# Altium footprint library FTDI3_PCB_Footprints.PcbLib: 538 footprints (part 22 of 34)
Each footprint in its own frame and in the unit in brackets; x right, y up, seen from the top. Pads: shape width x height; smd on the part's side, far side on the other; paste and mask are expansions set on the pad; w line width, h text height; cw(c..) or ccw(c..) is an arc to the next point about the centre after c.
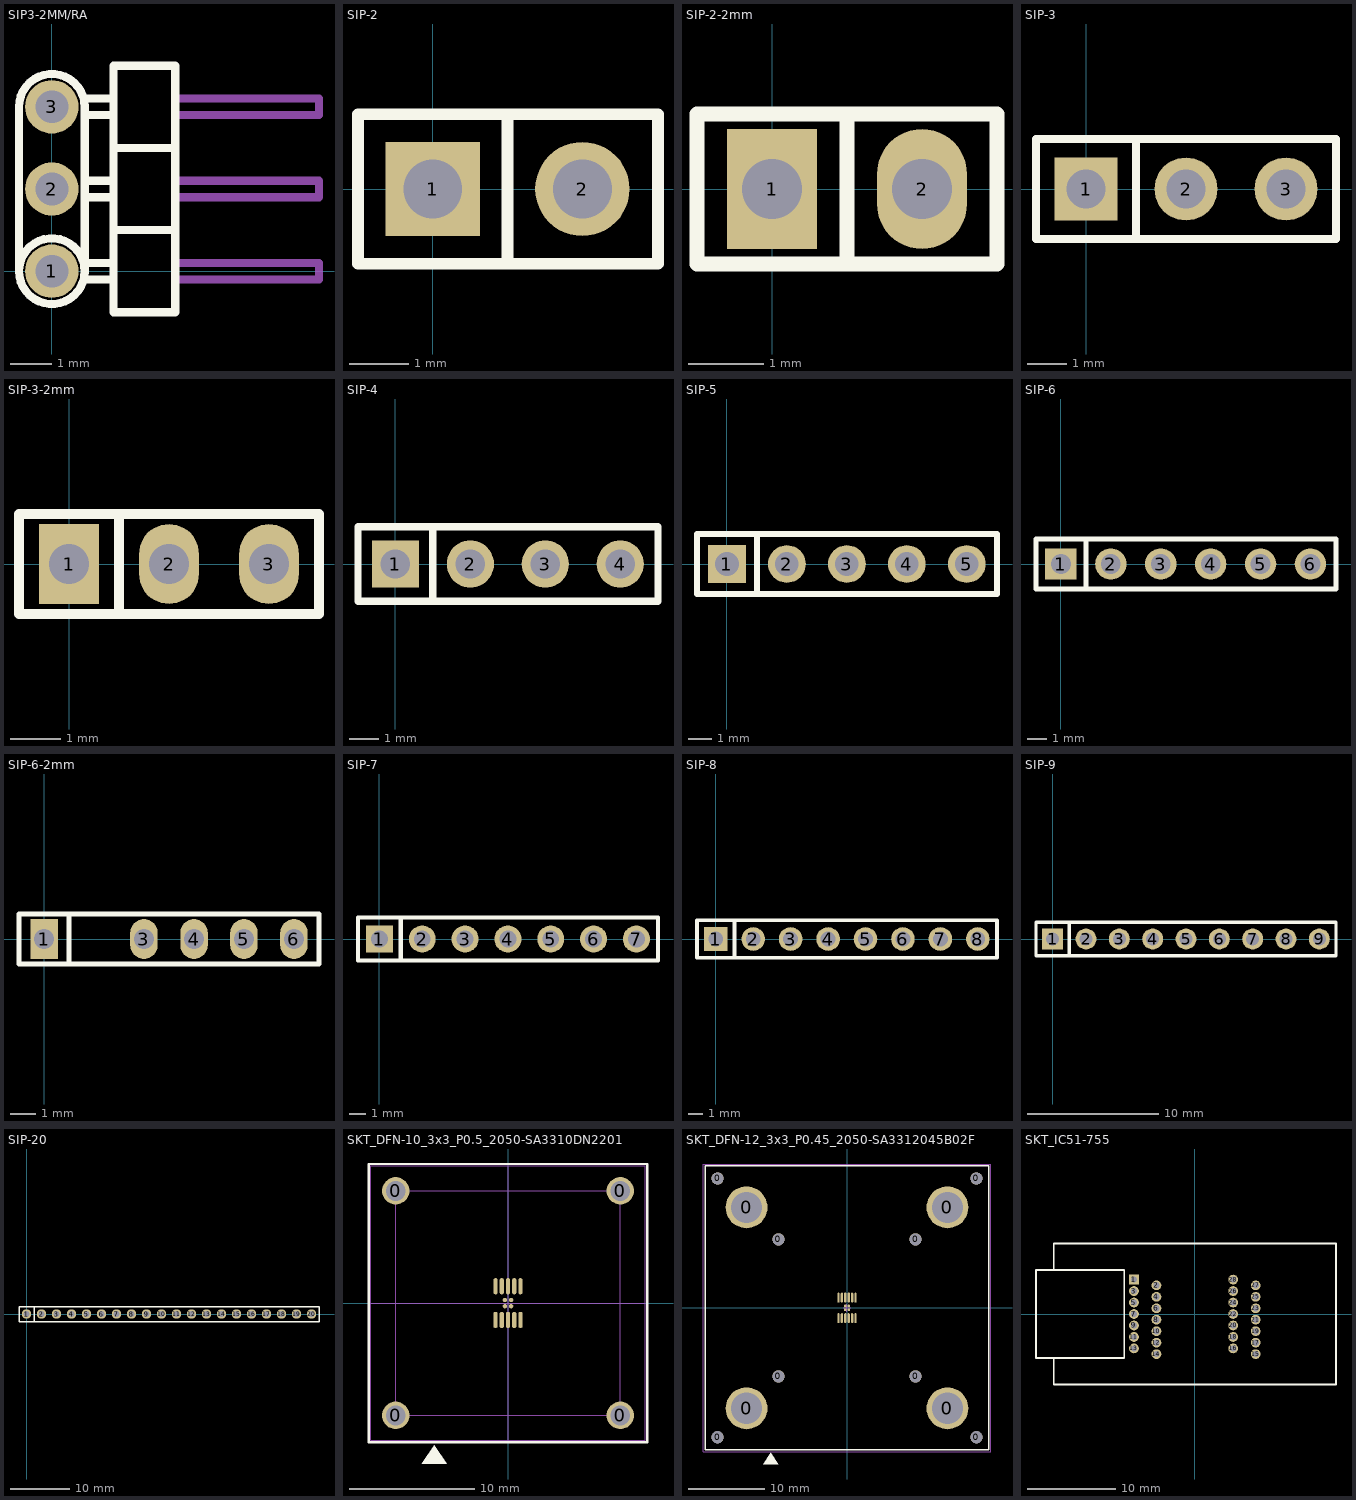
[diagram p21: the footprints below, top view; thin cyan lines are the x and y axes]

## SIP3-2MM/RA [mm] "Right Angle 2mm 3 way header"
pads (3):
  round 1.3 hole 0.8: 1(0,0) 2(0,2) 3(0,4)
Top Overlay:
  lines w0.2: 0.8,-0.2 1.5,-0.2 ; 0.8,0.2 1.5,0.2 ; 0.8,1.8 1.5,1.8 ; 0.8,2.2 1.5,2.2 ; 0.8,3.8 1.5,3.8 ; 0.8,4.2 1.5,4.2 ; 1.5,1 3,1 ; 1.5,3 3,3 ; -0.8,0 cw(c0,0) 0.8,0 ; -0.8,0 ccw(c0,0) 0.8,0 ; -0.8,0 -0.8,4 cw(c0,4) 0.8,4 0.8,0 ; 1.5,-1 3,-1 3,5 1.5,5 1.5,-1
M13_Assembly_Info:
  lines w0.2: 3,-0.2 6.5,-0.2 6.5,0.2 3,0.2 ; 3,1.8 6.5,1.8 6.5,2.2 3,2.2 ; 3,3.8 6.5,3.8 6.5,4.2 3,4.2

## SIP-2 [mm] "2 possition jumper; 0.1\" pitch"
pads (2):
  rect 1.6x1.6 hole 1: 1(0,0)
  round 1.6 hole 1: 2(2.54,0)
Top Overlay:
  lines w0.2: 1.27,-1.27 1.27,1.27 ; -1.27,-1.27 3.825,-1.27 3.825,1.27 -1.27,1.27 -1.27,-1.27
M13_Assembly_Info:
  lines w0.1: -1.27,-1.27 3.825,-1.27 3.825,1.27 -1.27,1.27 -1.27,-1.27
3D body: height 0, standoff 0, extent -1.27,-1.27 3.825,1.27

## SIP-2-2mm [mm] "Header, 2 pin, pitch 2.0mm"
pads (2):
  rect 1.2x1.6 hole 0.8: 1(0,0)
  oval 1.2x1.6 hole 0.8: 2(2,0)
Top Overlay:
  lines w0.2: 1,-1 1,1 ; -1,-1 3,-1 3,1 -1,1 -1,-1
3D body: height 6.5, standoff 0, extent -0.9,-0.9 2.9,0.9

## SIP-3 [mm] "3 possition jumper; pitch 0.1\""
pads (3):
  rect 1.6x1.6 hole 1: 1(0,0)
  round 1.6 hole 1: 2(2.54,0) 3(5.08,0)
Top Overlay:
  lines w0.2: 1.27,-1.27 1.27,1.27 ; -1.27,-1.27 6.35,-1.27 6.35,1.27 -1.27,1.27 -1.27,-1.27
M13_Assembly_Info:
  lines w0.1: -1.27,-1.27 6.35,-1.27 6.35,1.27 -1.27,1.27 -1.27,-1.27
3D body: height 0, standoff 0, extent -1.27,-1.27 6.35,1.27

## SIP-3-2mm [mm] "Header, 3 pin, pitch 2.0mm"
pads (3):
  rect 1.2x1.6 hole 0.8: 1(0,0)
  oval 1.2x1.6 hole 0.8: 2(2,0) 3(4,0)
Top Overlay:
  lines w0.2: 1,-1 1,1 ; -1,-1 -1,1 5,1 5,-1 -1,-1
3D body: height 6.5, standoff 0, extent -0.9,-0.9 4.9,0.9

## SIP-4 [mm] "Header; 4pin; pitch 0.1\""
pads (4):
  rect 1.6x1.6 hole 1: 1(0,0)
  round 1.6 hole 1: 2(2.54,0) 3(5.08,0) 4(7.62,0)
Top Overlay:
  lines w0.254: 1.27,-1.27 1.27,1.27 ; -1.27,-1.27 8.9,-1.27 8.9,1.27 -1.27,1.27 -1.27,-1.27
3D body: height 6.5, standoff 0, extent -1.15,-1.15 8.77,1.16

## SIP-5 [mm] "Header; 5 pin; pitch 0.1\""
pads (5):
  rect 1.6x1.6 hole 1: 1(0,0)
  round 1.6 hole 1: 2(2.54,0) 3(5.08,0) 4(7.62,0) 5(10.16,0)
Top Overlay:
  lines w0.254: 1.27,-1.27 1.27,1.27 ; -1.27,-1.27 -1.27,1.27 11.44,1.27 11.44,-1.27 -1.27,-1.27
3D body: height 6.5, standoff 0, extent -1.15,-1.15 11.325,1.15

## SIP-6 [mm] "Header, 6 pin, pitch 0.1\""
pads (6):
  rect 1.6x1.6 hole 1: 1(0,0)
  round 1.6 hole 1: 2(2.54,0) 3(5.08,0) 4(7.62,0) 5(10.16,0) 6(12.7,0)
Top Overlay:
  lines w0.254: 1.27,-1.27 1.27,1.27 ; -1.27,-1.27 -1.27,1.27 14,1.27 14,-1.27 -1.27,-1.27
3D body: height 6.5, standoff 0, extent -1.15,-1.15 13.875,1.15

## SIP-6-2mm [mm] "Header, 6 pin, pitch 2.0mm; pin 2 blind; for VII debugger module"
pads (5):
  rect 1.1x1.6 hole 0.8: 1(0,0)
  oval 1.1x1.6 hole 0.8: 3(4,0) 4(6,0) 5(8,0) 6(10,0)
Top Overlay:
  lines w0.2: 1,-1 1,1 ; -1,-1 -1,1 11,1 11,-1 -1,-1
3D body: height 6.5, standoff 0, extent -0.9,-0.9 10.9,0.9

## SIP-7 [mm] "Header, 7 pin, pitch 0.1\""
pads (7):
  rect 1.6x1.6 hole 1: 1(0,0)
  round 1.6 hole 1: 2(2.54,0) 3(5.08,0) 4(7.62,0) 5(10.16,0) 6(12.7,0) 7(15.24,0)
Top Overlay:
  lines w0.254: 1.27,-1.27 1.27,1.27 ; -1.27,-1.27 16.52,-1.27 16.52,1.27 -1.27,1.27 -1.27,-1.27
3D body: height 6.5, standoff 0, extent -1.15,-1.15 16.39,1.15

## SIP-8 [mm] "Header, 8 pin, pitch 0.1\""
pads (8):
  rect 1.6x1.6 hole 1: 1(0,0)
  round 1.6 hole 1: 2(2.54,0) 3(5.08,0) 4(7.62,0) 5(10.16,0) 6(12.7,0) 7(15.24,0) 8(17.78,0)
Top Overlay:
  lines w0.254: 1.27,-1.27 1.27,1.27 ; -1.27,-1.27 -1.27,1.27 19.08,1.27 19.08,-1.27 -1.27,-1.27
3D body: height 6.5, standoff 0, extent -1.15,-1.15 18.975,1.15

## SIP-9 [mm] "Resistor array"
pads (9):
  rect 1.6x1.6 hole 1: 1(0,0)
  round 1.6 hole 1: 2(2.54,0) 3(5.08,0) 4(7.62,0) 5(10.16,0) 6(12.7,0) 7(15.24,0) 8(17.78,0) 9(20.32,0)
Top Overlay:
  lines w0.254: 1.27,-1.27 1.27,1.27 ; -1.27,-1.27 -1.27,1.27 21.59,1.27 21.59,-1.27 -1.27,-1.27

## SIP-20 [mm]
pads (20):
  round 1.6 hole 1: 1(0,0) 2(2.54,0) 3(5.08,0) 4(7.62,0) 5(10.16,0) 6(12.7,0) 7(15.24,0) 8(17.78,0) 9(20.32,0) 10(22.86,0) 11(25.4,0) 12(27.94,0) 13(30.48,0) 14(33.02,0) 15(35.56,0) 16(38.1,0) 17(40.64,0) 18(43.18,0) 19(45.72,0) 20(48.26,0)
Top Overlay:
  lines w0.254: 1.27,-1.27 1.27,1.27 ; -1.27,-1.27 49.53,-1.27 49.53,1.27 -1.27,1.27 -1.27,-1.27

## SKT_DFN-10_3x3_P0.5_2050-SA3310DN2201 [mm] "Tai-Chen Precision Inc. DFN-10 3x3mm body; 0.5mm pitch; Test Socket; 2050-SA3310DN2201"
height 6.6
pads (18):
  round 2.2 hole 1.6: 0(-9,-9) 0(-9,9) 0(9,-9) 0(9,9)
  oval 0.35x1.3 smd: 1(-1,-1.35) 2(-0.5,-1.35) 3(0,-1.35) 4(0.5,-1.35) 5(1,-1.35) 6(1,1.35) 7(0.5,1.35) 8(0,1.35) 9(-0.5,1.35) 10(-1,1.35)
  round 0.35 smd: 11(-0.25,-0.25) 11(-0.25,0.25) 11(0.25,-0.25) 11(0.25,0.25)
Top Overlay:
  region: -5.9,-11.4 -4.9,-12.9 -6.9,-12.9
  lines w0.2: -11.15,-11.14 -11.15,11.15 11.15,11.15 11.15,-11.14 -11.15,-11.14
Top Solder:
  region: 11,-11 -11,-11 -11,11 11,11
M15_Country_Yard:
  lines w0.1: -11,0 11,0 ; -9,0 9,0 ; -0.5,0 0.5,0 ; 0,-11 0,11 ; 0,-9 0,9 ; 0,-0.5 0,0.5 ; -11,-11 -11,11 11,11 11,-11 -11,-11 ; -9,-9 -9,9 9,9 9,-9 -9,-9

## SKT_DFN-12_3x3_P0.45_2050-SA3312045B02F [mm] "Tai-Chen Precision Inc. DFN-12 3x3mm body; 0.45mm pitch; Test Socket; 2050-SA3312045B02F"
height 6.6
pads (28):
  round 1.6 hole 1.6 unplated: 0(-17,-17) 0(-17,17) 0(-9,-9) 0(-9,9) 0(9,-9) 0(9,9) 0(17,-17) 0(17,17)
  round 5.5 hole 4.1: 0(-13.2,-13.2) 0(-13.2,13.2) 0(13.2,-13.2) 0(13.2,13.2)
  oval 0.3x1.3 smd: 1(-1.125,-1.35) 2(-0.675,-1.35) 3(-0.225,-1.35) 4(0.225,-1.35) 5(0.675,-1.35) 6(1.125,-1.35) 7(1.125,1.35) 8(0.675,1.35) 9(0.225,1.35) 10(-0.225,1.35) 11(-0.675,1.35) 12(-1.125,1.35)
  round 0.35 smd: 13(-0.25,-0.25) 13(-0.25,0.25) 13(0.25,-0.25) 13(0.25,0.25)
Top Overlay:
  region: -10,-19.01 -9,-20.51 -11,-20.51
  lines w0.2: -18.65,-18.65 18.65,-18.65 18.65,18.65 -18.65,18.65 -18.65,-18.65
Top Solder:
  region: 18.5,-18.5 -18.5,-18.5 -18.5,18.5 18.5,18.5
M15_Country_Yard:
  lines w0.1: -0.5,0 0.5,0 ; 0,-0.5 0,0.5 ; -18.9,-18.9 -18.9,18.9 18.9,18.9 18.9,-18.9 -18.9,-18.9

## SKT_IC51-755 [mm] "CLAMSHELL SOCKET 28PIN SSOP"
height 20
pads (28):
  rect 1.1x1.1 hole 0.7: 1(-6.9,3.9)
  round 1.1 hole 0.7: 2(-4.35,3.25) 3(-6.9,2.6) 4(-4.35,1.95) 5(-6.9,1.3) 6(-4.35,0.65) 7(-6.9,0) 8(-4.35,-0.65) 9(-6.9,-1.3) 10(-4.35,-1.95) 11(-6.9,-2.6) 12(-4.35,-3.25) 13(-6.9,-3.9) 14(-4.35,-4.55) 15(6.9,-4.55) 16(4.35,-3.9) 17(6.9,-3.25) 18(4.35,-2.6) 19(6.9,-1.95) 20(4.35,-1.3) 21(6.9,-0.65) 22(4.35,0) 23(6.9,0.65) 24(4.35,1.3) 25(6.9,1.95) 26(4.35,2.6) 27(6.9,3.25) 28(4.35,3.9)
Top Overlay:
  lines w0.2: -16,-5 -16,-8 16,-8 16,8 -16,8 -16,5 ; -18,-5 -8,-5 -8,5 -18,5 -18,-5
